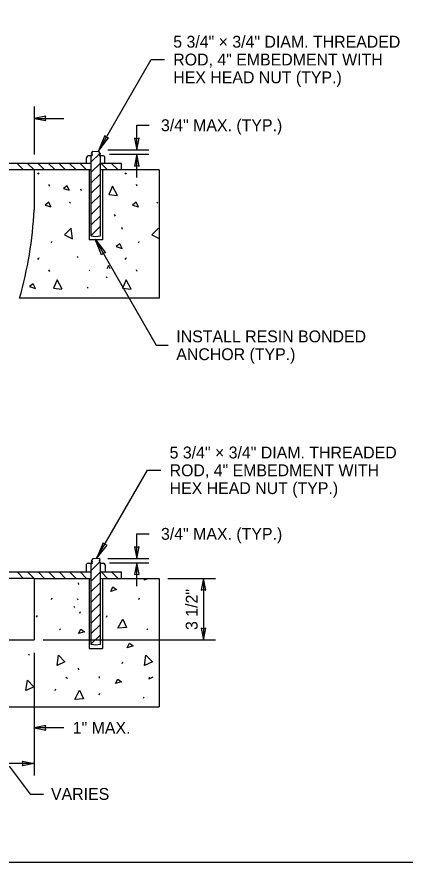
# Model space of a CAD drawing. Extents: x 99862 to 103151, y 100000 to 102076.
# Drawn here: x 100819 to 101342, y 100000 to 101138 of the extents above; entities that cross this region are included whole.
import ezdxf

# ---------------------------------------------------------------- set-up
doc = ezdxf.new("R2010")
doc.units = 0
for name, color, linetype in [('Level 1', 7, 'Continuous'), ('Level 13', 7, 'Continuous'), ('Level 15', 7, 'Continuous'), ('Level 17', 7, 'Continuous'), ('Level 18', 7, 'Continuous'), ('Level 20', 7, 'Continuous')]:
    doc.layers.add(name, color=color, linetype=linetype)

msp = doc.modelspace()

# ---------------------------------------------------------------- linework, layer by layer
at = {"layer": 'Level 1'}
for p, q in [((100919.8, 100955.5), (100921.6, 100956.9)), ((100921.6, 100956.9), (100929.8, 100956.8)), ((100929.8, 100956.8), (100930.5, 100956.1)), ((100912.8, 100940.7), (100912.8, 100948.7)), ((100919.6, 100950.7), (100915, 100950.7)), ((100919.4, 100950.8), (100921, 100952.1)), ((100919.9, 100950.6), (100919.4, 100950.8)), ((100919.5, 100953.5), (100920.9, 100954.4)), ((100921, 100952.1), (100919.5, 100953.5)), ((100919.5, 100843.2), (100919.5, 100950.7)), ((100920.9, 100954.4), (100919.8, 100955.5)), ((100930.5, 100956.1), (100929.8, 100955.5)), ((100929.8, 100955.5), (100931.7, 100954)), ((100931.7, 100951.7), (100930, 100950.6)), ((100931.7, 100954), (100930.2, 100953.2)), ((100930.2, 100953.2), (100931.7, 100951.7)), ((100935.9, 100950.7), (100930.3, 100950.7)), ((100931.8, 100843.2), (100931.8, 100950.7)), ((100937.9, 100940.7), (100937.9, 100949.6)), ((100919.5, 100940.7), (100724.9, 100940.7)), ((100960.1, 100940.7), (100931.8, 100940.7)), ((100960.1, 100932), (100960.1, 100940.7)), ((100842.5, 100932), (100278.9, 100932)), ((100916.8, 100932), (100916.8, 100837.8)), ((100934.5, 100932), (100934.5, 100837.8)), ((100934.5, 100837.8), (100916.8, 100837.8)), ((100913.2, 100390.3), (100913.2, 100401)), ((100915.3, 100402.1), (100921, 100402.1)), ((100921.4, 100407), (100919.5, 100405.5)), ((100919.5, 100405.5), (100921, 100404.6)), ((100921, 100404.6), (100919.5, 100403.2)), ((100919.5, 100403.2), (100921, 100402.1)), ((100919.5, 100292.7), (100919.5, 100402.1)), ((100921.4, 100408.2), (100920.7, 100407.5)), ((100920.7, 100407.5), (100921.4, 100407)), ((100929.6, 100408.4), (100921.4, 100408.2)), ((100931.4, 100407), (100929.6, 100408.4)), ((100930.1, 100403.5), (100931.6, 100405)), ((100931.7, 100402.3), (100930.1, 100403.5)), ((100930.3, 100405.9), (100931.4, 100407)), ((100931.6, 100405), (100930.3, 100405.9)), ((100931.5, 100402.1), (100931.7, 100402.3)), ((100931.5, 100402.1), (100936.1, 100402.1)), ((100931.8, 100292.7), (100931.8, 100402.1)), ((100938.4, 100390.3), (100938.4, 100400.1)), ((100724.9, 100390.3), (100919.5, 100390.3)), ((100931.8, 100390.3), (100960.1, 100390.3)), ((100931.8, 100381.5), (100931.8, 100390.3)), ((100960.1, 100381.5), (100960.1, 100390.3)), ((100842.5, 100381.5), (100278.9, 100381.5)), ((100916.8, 100381.5), (100916.8, 100287.3)), ((100934.4, 100381.5), (100934.4, 100287.3)), ((100916.8, 100287.3), (100934.4, 100287.3))]:
    msp.add_line(p, q, dxfattribs=at)
msp.add_lwpolyline([(99862, 99999.5), (103151, 99999.5), (103151, 102075.5), (99862, 102075.5)], close=True, dxfattribs=at)
for points in [[(100919.5, 100843.2), (100925.6, 100842.2), (100931.8, 100843.2)], [(100931.8, 100292.7), (100925.6, 100291.7), (100919.5, 100292.7)]]:
    msp.add_lwpolyline(points, dxfattribs=at)
for centre, radius, start, end in [((100916.5, 100946.8), 4.13, 110.2056, 152.5283), ((100935.9, 100948.3), 2.33, 32.6964, 91.7041), ((100915.2, 100399.8), 2.33, 88.2959, 147.3036), ((100934.7, 100398.2), 4.13, 27.4717, 69.7944)]:
    msp.add_arc(centre, radius, start, end, dxfattribs=at)
at = {"layer": 'Level 13'}
for p, q in [((100842.5, 100932), (100842.5, 100877.9)), ((100919.5, 100932), (100842.5, 100932)), ((101010.7, 100932), (100931.8, 100932)), ((101010.7, 100932), (101010.7, 100759.1)), ((101010.7, 100759.1), (100822.9, 100759.1)), ((100842.5, 100381.5), (100919.5, 100381.5)), ((100842.5, 100381.5), (100842.5, 100298.9)), ((100931.8, 100381.5), (101010.7, 100381.5)), ((101010.7, 100381.5), (101010.7, 100208.7)), ((100769.4, 100298.9), (100842.5, 100298.9)), ((100649.7, 100208.7), (101010.7, 100208.7))]:
    msp.add_line(p, q, dxfattribs=at)
msp.add_arc((100309.5, 100904.9), 533.7, 344.1462, 357.0991, dxfattribs=at)
at = {"layer": 'Level 15'}
for p, q in [((100928.8, 100956.8), (101000.3, 101080.5)), ((101000.3, 101080.5), (101017.9, 101080.5)), ((100842.5, 101017.3), (100842.5, 100952.7)), ((100842.5, 101001.3), (100882.5, 101001.3)), ((100980.9, 100958.8), (100980.9, 100992)), ((100980.9, 100992), (100997.4, 100992)), ((100941.6, 100958.8), (100996.9, 100958.8)), ((100943.8, 100952.9), (100996.9, 100952.9)), ((100980.9, 100921.6), (100980.9, 100952.9)), ((100924.5, 100838.6), (101007.1, 100695.6)), ((101007.1, 100695.6), (101023.1, 100695.6)), ((100926.7, 100408.3), (100995.4, 100527.2)), ((100995.4, 100527.2), (101013, 100527.2)), ((100980.9, 100408.4), (100980.9, 100441.6)), ((100980.9, 100441.6), (100997.4, 100441.6)), ((100941.6, 100408.4), (100996.9, 100408.4)), ((100943.8, 100402.4), (100996.9, 100402.4)), ((100980.9, 100371.2), (100980.9, 100402.4)), ((101022.7, 100381.5), (101086.7, 100381.5)), ((101070.7, 100381.5), (101070.7, 100298.9)), ((100854.5, 100298.9), (101086.7, 100298.9)), ((100842.5, 100281.2), (100842.5, 100116.3)), ((100882.5, 100180.4), (100842.5, 100180.4)), ((100842.5, 100132.3), (100769.4, 100132.3)), ((100808.7, 100128.7), (100837.3, 100090.9)), ((100837.3, 100090.9), (100854.9, 100090.9))]:
    msp.add_line(p, q, dxfattribs=at)
for points in [[(100842.5, 101001.3), (100858.2, 100998.2), (100857.5, 101001.3), (100858.2, 101004.4)], [(100928.8, 100956.8), (100942.8, 100975.1), (100939.7, 100975.7), (100937.7, 100978.1)], [(100980.9, 100958.8), (100984, 100974.5), (100980.9, 100973.8), (100977.8, 100974.5)], [(100980.9, 100952.9), (100977.8, 100937.1), (100980.9, 100937.9), (100984, 100937.1)], [(100924.5, 100838.6), (100938.5, 100820.3), (100935.4, 100819.8), (100933.3, 100817.4)], [(100926.7, 100408.3), (100940.7, 100426.6), (100937.6, 100427.2), (100935.5, 100429.6)], [(100980.9, 100408.4), (100984, 100424.1), (100980.9, 100423.4), (100977.8, 100424.1)], [(100980.9, 100402.4), (100977.8, 100386.7), (100980.9, 100387.4), (100984, 100386.7)], [(101070.7, 100381.5), (101067.6, 100365.8), (101070.7, 100366.5), (101073.8, 100365.8)], [(101070.7, 100298.9), (101073.8, 100314.7), (101070.7, 100313.9), (101067.6, 100314.7)], [(100842.5, 100180.4), (100858.2, 100177.3), (100857.5, 100180.4), (100858.2, 100183.5)], [(100842.5, 100132.3), (100826.8, 100129.2), (100827.5, 100132.3), (100826.8, 100135.4)]]:
    msp.add_lwpolyline(points, close=True, dxfattribs=at)
at = {"layer": 'Level 17'}
for p, q in [((100848, 100927.5), (100847, 100926)), ((100849, 100928), (100848, 100926.6)), ((100965.7, 100927.5), (100964.7, 100926)), ((100966.6, 100928), (100965.7, 100926.6)), ((100863.5, 100909.8), (100862.4, 100912)), ((100981.2, 100909.8), (100980.2, 100912)), ((100906.4, 100903.7), (100905.5, 100905.9)), ((100890.9, 100888.4), (100890, 100887)), ((101008.7, 100888.4), (101007.7, 100887)), ((100951.9, 100869.5), (100950.9, 100871.8)), ((100961.5, 100851.8), (100960.5, 100854.1)), ((100865.7, 100835.6), (100865.5, 100833.4)), ((100983.4, 100835.6), (100983.2, 100833.4)), ((100848, 100812.7), (100847, 100811.2)), ((100849, 100813.2), (100848, 100811.8)), ((100901.8, 100813.2), (100900.8, 100815.4)), ((100965.7, 100812.7), (100964.7, 100811.2)), ((100966.6, 100813.2), (100965.7, 100811.8)), ((100863.5, 100795), (100862.4, 100797.2)), ((100981.2, 100795), (100980.2, 100797.2)), ((100917.4, 100796.1), (100917.1, 100796.9)), ((100940.5, 100788), (100939.6, 100786.5)), ((100914.7, 100774), (100913.7, 100772.6)), ((100901.8, 100375.6), (100902.1, 100373.3)), ((100865.8, 100353.2), (100866.7, 100355.4)), ((100900.3, 100354.4), (100901.3, 100352.9)), ((100983.4, 100353.2), (100984.5, 100355.4)), ((100896.1, 100343.9), (100897.1, 100342.4)), ((100845.8, 100329.3), (100846.8, 100331.6)), ((100904.1, 100335), (100905.1, 100337.2)), ((100940.1, 100329.3), (100941, 100331.6)), ((100876.5, 100313.6), (100877.5, 100312.2)), ((100994.3, 100313.6), (100995.3, 100312.2)), ((100834.8, 100279.9), (100835.7, 100278.4)), ((100961.1, 100266.9), (100962.1, 100269.2)), ((100901.8, 100260.8), (100902.1, 100258.6)), ((100885.3, 100248.9), (100886.2, 100247.4)), ((100886.2, 100248.3), (100887.2, 100246.9)), ((100929.9, 100249.5), (100930.1, 100247.3)), ((100870.7, 100230.7), (100871.8, 100232.9)), ((100930.2, 100225), (100931.2, 100227.2)), ((100989.9, 100220.1), (100990.9, 100222.3))]:
    msp.add_line(p, q, dxfattribs=at)
for points in [[(100889.7, 100904.5), (100886.8, 100910.6), (100881.9, 100906.9), (100889.7, 100904.5)], [(100954.9, 100897.5), (100948.2, 100910), (100943, 100898.5), (100954.6, 100897.5)], [(100865.1, 100882.1), (100862.2, 100888.2), (100857.3, 100884.5), (100865.1, 100882.1)], [(100982.9, 100882.1), (100979.9, 100888.2), (100975, 100884.5), (100982.9, 100882.1)], [(100894.3, 100839.2), (100892.3, 100853.2), (100883.5, 100844.2), (100894, 100839.2)], [(101010, 100853.2), (101001.2, 100844.2), (101009.9, 100840.1)], [(100961, 100826), (100958.1, 100832.1), (100953.1, 100828.5), (100961, 100826)], [(100944.9, 100798.7), (100942.6, 100803.1), (100940.6, 100798.7)], [(100844.1, 100772.2), (100841.1, 100778.3), (100836.2, 100774.7), (100844.1, 100772.2)], [(100880.2, 100771.4), (100873.6, 100784), (100868.5, 100772.5), (100880, 100771.4)], [(100973.2, 100771.4), (100966.6, 100784), (100961.4, 100772.5), (100973, 100771.4)], [(100991, 100379.2), (100991.3, 100381.5)], [(100996, 100381.5), (100991.3, 100379.3)], [(100945.7, 100364.2), (100948.6, 100370.3), (100953.6, 100366.6), (100945.7, 100364.2)], [(100955.2, 100314.4), (100961.8, 100326.9), (100967, 100315.4), (100955.5, 100314.4)], [(100902.4, 100307.3), (100905.3, 100313.4), (100910.2, 100309.7), (100902.4, 100307.3)], [(100968, 100288.3), (100970.9, 100294.4), (100975.8, 100290.8), (100968, 100288.3)], [(100873.3, 100264.4), (100875.2, 100278.4), (100884, 100269.4), (100873.5, 100264.5)], [(100991, 100264.4), (100992.9, 100278.4), (101001.8, 100269.4), (100991.3, 100264.5)], [(100831.5, 100230.6), (100833.5, 100244.6), (100842.2, 100235.6), (100831.7, 100230.7)], [(100952.3, 100240), (100955.2, 100246.1), (100960.1, 100242.4), (100952.3, 100240)], [(100997.5, 100246.1), (100997.8, 100248.4)], [(101002.4, 100248.4), (100997.7, 100246.2)], [(100897.1, 100218.4), (100903.7, 100230.9), (100908.9, 100219.4), (100897.3, 100218.4)]]:
    msp.add_lwpolyline(points, dxfattribs=at)
at = {"layer": 'Level 18'}
for p, q in [((100930.5, 100953.7), (100919.5, 100942.7)), ((100828.3, 100932), (100819.5, 100940.7)), ((100842.4, 100932), (100833.6, 100940.7)), ((100856.6, 100932), (100847.8, 100940.7)), ((100870.7, 100932), (100861.9, 100940.7)), ((100884.9, 100932), (100876.1, 100940.7)), ((100899, 100932), (100890.2, 100940.7)), ((100913.1, 100932), (100904.4, 100940.7)), ((100931.8, 100940.8), (100919.5, 100928.6)), ((100941.4, 100932), (100932.6, 100940.7)), ((100955.6, 100932), (100946.8, 100940.7)), ((100931.8, 100926.7), (100919.5, 100914.4)), ((100931.8, 100912.5), (100919.5, 100900.3)), ((100931.8, 100898.4), (100919.5, 100886.1)), ((100931.8, 100884.3), (100919.5, 100872)), ((100931.8, 100870.1), (100919.5, 100857.8)), ((100931.8, 100856), (100919.5, 100843.7)), ((100930.5, 100403.3), (100919.5, 100392.3)), ((100828.3, 100381.5), (100819.5, 100390.3)), ((100842.4, 100381.5), (100833.6, 100390.3)), ((100856.6, 100381.5), (100847.8, 100390.3)), ((100870.7, 100381.5), (100861.9, 100390.3)), ((100884.8, 100381.5), (100876.1, 100390.3)), ((100899, 100381.5), (100890.2, 100390.3)), ((100913.1, 100381.5), (100904.3, 100390.3)), ((100919.5, 100389.3), (100918.5, 100390.3)), ((100931.8, 100390.4), (100919.5, 100378.1)), ((100941.4, 100381.5), (100932.6, 100390.3)), ((100955.6, 100381.5), (100946.8, 100390.3)), ((100931.8, 100376.2), (100919.5, 100364)), ((100931.8, 100362.1), (100919.5, 100349.8)), ((100931.8, 100348), (100919.5, 100335.7)), ((100931.8, 100333.8), (100919.5, 100321.5)), ((100931.8, 100319.7), (100919.5, 100307.4)), ((100931.8, 100305.5), (100919.5, 100293.3))]:
    msp.add_line(p, q, dxfattribs=at)

# ---------------------------------------------------------------- texts
at = {"layer": 'Level 20'}
for s, p in [('5 3/4" × 3/4" DIAM. THREADED', (101029.9, 101096.5)), ('ROD, 4" EMBEDMENT WITH', (101029.9, 101072.5)), ('HEX HEAD NUT (TYP.)', (101029.9, 101048.5)), ('3/4" MAX. (TYP.)', (101013.4, 100984)), ('INSTALL RESIN BONDED', (101034, 100699.6)), ('ANCHOR (TYP.)', (101034, 100675.6)), ('5 3/4" × 3/4" DIAM. THREADED', (101025, 100543.2)), ('ROD, 4" EMBEDMENT WITH', (101025, 100519.2)), ('HEX HEAD NUT (TYP.)', (101025, 100495.2)), ('3/4" MAX. (TYP.)', (101013.4, 100433.6)), ('1" MAX.', (100894.5, 100172.4)), ('VARIES', (100865.2, 100083.3))]:
    msp.add_text(s, height=16, dxfattribs=at).set_placement(p)
msp.add_text('3 1/2"', height=16, rotation=90, dxfattribs=at).set_placement((101062.7, 100312.1))

doc.saveas('drawing.dxf')
